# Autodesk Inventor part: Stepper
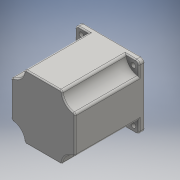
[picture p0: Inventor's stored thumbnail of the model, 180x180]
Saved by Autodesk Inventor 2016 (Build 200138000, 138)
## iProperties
Created: 2016-02
Part Number: Stepper
Material: Generic
Document SubType Name: Modeling
Designer: Juha-Pekka
Density: 1 g/cm^3
Appearance: Default
Author: Juha-Pekka
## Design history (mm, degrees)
sketch "Sketch1"
  geometry: L1 (44.5, -56)-(11.5, -56); L2 (56, -11.5)-(56, -44.5); L3 (11.5, 0)-(44.5, 0); L4 (0, -44.5)-(0, -11.5); A1 r 11.5 centre (56, -56) between (56, -44.5) and (44.5, -56); A2 r 11.5 centre (56, 0) between (44.5, 0) and (56, -11.5); A3 r 11.5 centre (0, -56) between (11.5, -56) and (0, -44.5); A4 r 11.5 centre (0, 0) between (0, -11.5) and (11.5, 0); 1 further point
  constraints: 8 end point, 8 point on circle, 4 centre point, 2 parallel, 1 coincident, 1 horizontal, 1 perpendicular
extrude "Extrusion1" new body sketch "Sketch1" distance "d6" = 56; taper "d7" = 0 deg
fillet "Fillet1" dims "d10" = 2
sketch "Sketch7"
  geometry: L1 (0, 0)-(-56, 0); L2 (-56, 0)-(-56, 56); L3 (-56, 56)-(0, 56); L4 (0, 56)-(0, 0)
  constraints: 8 end point, 2 parallel, 1 horizontal, 1 perpendicular
  dimensions: "d16" = 56 distance of L2.end L3.end; "d17" = 56 distance of L1.end L2.end
extrude "Extrusion5" join sketch "Sketch7" distance "d18" = 5; taper "d19" = 0 deg
fillet "Fillet3" dims "d20" = 3
fillet "Fillet4" dims "d21" = 1
fillet "Fillet5" dims "d22" = 1
hole "Hole1" diameter "d25" = 4; stored, may be unused: countersink angle "d29" = 90 deg, drill point angle "d31" = 118 deg; dims "d23" = 10, "d24" = 10, "d26" = 6, "d27" = 4, "d28" = 2, "d30" = 8
hole "Hole2" diameter "d34" = 4; stored, may be unused: countersink angle "d38" = 90 deg, drill point angle "d40" = 118 deg; dims "d32" = 10, "d33" = 10, "d35" = 6, "d36" = 4, "d37" = 2, "d39" = 8
hole "Hole3" diameter "d43" = 4; stored, may be unused: countersink angle "d47" = 90 deg, drill point angle "d49" = 118 deg; dims "d41" = 10, "d42" = 10, "d44" = 6, "d45" = 4, "d46" = 2, "d48" = 8
hole "Hole4" diameter "d52" = 4; stored, may be unused: countersink angle "d56" = 90 deg, drill point angle "d58" = 118 deg; dims "d50" = 10, "d51" = 10, "d53" = 6, "d54" = 4, "d55" = 2, "d57" = 8
sketch "Sketch8"
  geometry: L1 (-55, 53)-(-55, 44.381) reference; L2 (-1, 3)-(0, 3) reference; L3 (-55, 3)-(-1, 53); L4 (-3, 1)-(-53, 1) reference; L5 (-53, 55)-(-3, 1); C1 r 19.229 at (-28, 28); A1 r 2 centre (-3, 53) between (-1, 53) and (-3, 55) reference; A2 r 2 centre (-53, 53) between (-53, 55) and (-55, 53) reference; 2 further points
  constraints: 4 end point, 1 centre point, 1 midpoint, 1 perpendicular
extrude "Extrusion6" join sketch "Sketch8" distance "d59" = 1; taper "d60" = 0 deg
sketch "Sketch9"
  geometry: C1 r 3 at (0, 0); 1 further point
  constraints: 1 centre point
  dimensions: "d61" = 6 diameter of C1
extrude "Extrusion7" join sketch "Sketch9" distance "d62" = 20; taper "d63" = 0 deg
fillet "Fillet6" dims "d64" = 1
body "Solid1"
